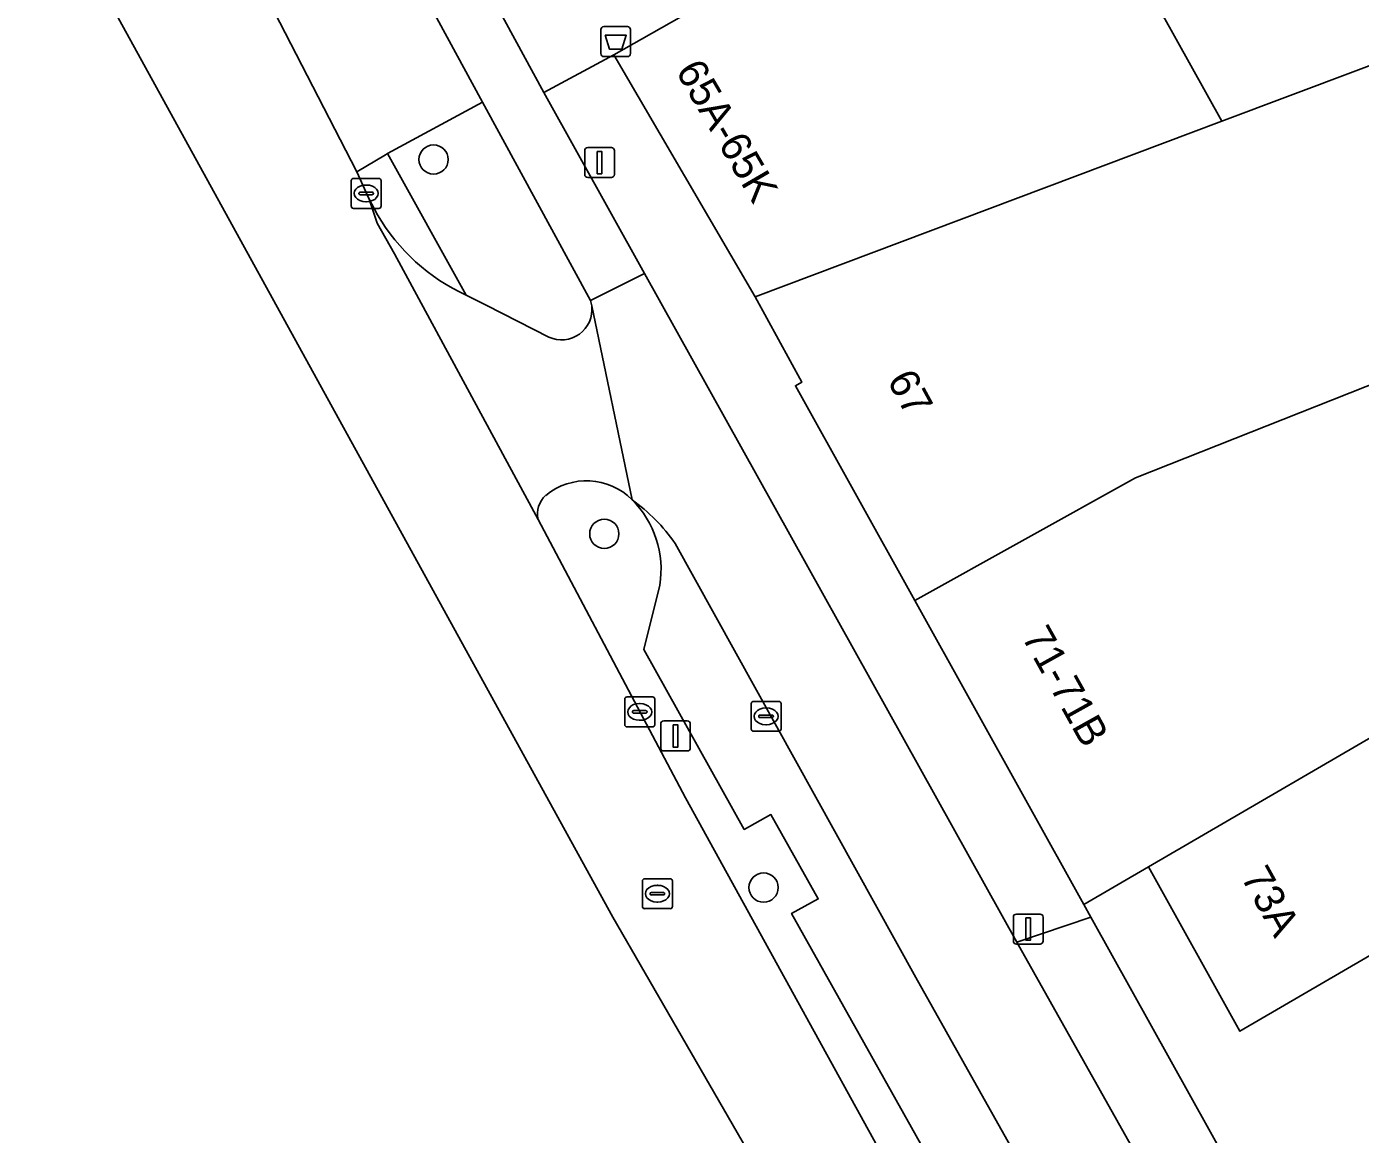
# Model space of a CAD drawing. Extents: x 161881 to 162523, y 381678 to 382381.
# Drawn here: x 162054.54 to 162099.12, y 381947.33 to 381984.36 of the extents above; entities that cross this region are included whole.
import ezdxf

# ---------------------------------------------------------------- set-up
doc = ezdxf.new("R2010")
doc.units = 0
for name, color, linetype in [('IMGEO_Afvalbak', 7, 'Continuous'), ('IMGEO_Berm_groen', 7, 'Continuous'), ('IMGEO_Boom', 7, 'Continuous'), ('IMGEO_Erf', 7, 'Continuous'), ('IMGEO_Fietspad_gesloten', 7, 'Continuous'), ('IMGEO_Fietspad_open', 7, 'Continuous'), ('IMGEO_Kolk', 7, 'Continuous'), ('IMGEO_Lichtmast', 7, 'Continuous'), ('IMGEO_Pand', 7, 'Continuous'), ('IMGEO_Pand_nummerreeks', 7, 'Continuous'), ('IMGEO_Parkeervlak_open', 7, 'Continuous'), ('IMGEO_Rijbaan_lokaal_gesloten', 7, 'Continuous'), ('IMGEO_Rioolput', 7, 'Continuous'), ('IMGEO_Voetpad_open', 7, 'Continuous')]:
    doc.layers.add(name, color=color, linetype=linetype)

msp = doc.modelspace()

# ---------------------------------------------------------------- linework, layer by layer
at = {"layer": 'IMGEO_Afvalbak'}
for p, q in [((162073.733, 381983.46), (162073.733, 381984.26)), ((162073.733, 381984.26), (162073.733, 381983.46)), ((162073.833, 381984.36), (162074.623, 381984.36)), ((162074.623, 381984.36), (162073.833, 381984.36)), ((162074.723, 381984.26), (162074.723, 381983.46)), ((162074.723, 381983.46), (162074.723, 381984.26)), ((162074.623, 381983.36), (162073.833, 381983.36)), ((162073.833, 381983.36), (162074.623, 381983.36))]:
    msp.add_line(p, q, dxfattribs=at)
msp.add_lwpolyline([(162073.876, 381984.074), (162074.58, 381984.074), (162074.431, 381983.604), (162074.025, 381983.604), (162073.876, 381984.074)], dxfattribs=at)
for centre, start, end in [((162073.833, 381984.26), 90, 180), ((162073.833, 381984.26), 90, 180), ((162074.623, 381984.26), 0, 90), ((162074.623, 381984.26), 360, 90), ((162073.833, 381983.46), 180, 270), ((162073.833, 381983.46), 180, 270), ((162074.623, 381983.46), 270, 0), ((162074.623, 381983.46), 270, 0)]:
    msp.add_arc(centre, 0.1, start, end, dxfattribs=at)
at = {"layer": 'IMGEO_Berm_groen'}
for points in [[(162069.775, 381981.832), (162066.606, 381980.116), (162069.236, 381975.383), (162069.927, 381975.036), (162071.998, 381973.982)], [(162073.43, 381975.024), (162073.393, 381975.201), (162069.775, 381981.832)], [(162071.636, 381967.886), (162076.565, 381958.577), (162107.811, 381901.826), (162108.729, 381902.414), (162110.128, 381903.311), (162108.772, 381905.652), (162107.884, 381905.166), (162102.118, 381915.454), (162102.985, 381915.921), (162101.417, 381918.762), (162100.535, 381918.293), (162094.757, 381928.54)], [(162094.757, 381928.54), (162095.649, 381929.029), (162094.05, 381931.846), (162093.19, 381931.352), (162087.448, 381941.624), (162088.219, 381942.206), (162086.738, 381944.939), (162085.861, 381944.447), (162080.108, 381954.721), (162080.998, 381955.203), (162079.42, 381958.024), (162078.528, 381957.526), (162075.168, 381963.546), (162075.702, 381965.694)]]:
    msp.add_lwpolyline(points, dxfattribs=at)
for centre, radius, start, end in [((162072.42, 381974.907), 1.017, 245.498, 6.5853), ((162073.252, 381967.033), 2.147, 44.7404, 129.3923), ((162072.448, 381968.074), 0.833, 132.1236, 193.0227), ((162072.473, 381966.221), 3.272, 350.727, 45.2358)]:
    msp.add_arc(centre, radius, start, end, dxfattribs=at)
at = {"layer": 'IMGEO_Boom'}
for centre in [(162068.144, 381979.919), (162073.85, 381967.407), (162079.174, 381955.584)]:
    msp.add_circle(centre, 0.489, dxfattribs=at)
at = {"layer": 'IMGEO_Erf'}
msp.add_lwpolyline([(162088.878, 381991.295), (162094.493, 381981.199), (162124.179, 381992.364)], dxfattribs=at)
at = {"layer": 'IMGEO_Fietspad_gesloten'}
msp.add_lwpolyline([(162062.41, 381995.394), (162069.775, 381981.832), (162073.393, 381975.201), (162075.194, 381976.109), (162071.825, 381982.158), (162067.605, 381989.931)], dxfattribs=at)
at = {"layer": 'IMGEO_Fietspad_open'}
for points in [[(162075.194, 381976.109), (162073.393, 381975.201), (162073.43, 381975.024), (162074.777, 381968.544)], [(162117.066, 381901.457), (162102.32, 381927.62), (162087.64, 381953.76), (162075.194, 381976.109)], [(162076.214, 381967.086), (162084.266, 381952.579), (162111.528, 381904.042)]]:
    msp.add_lwpolyline(points, dxfattribs=at)
msp.add_arc((162071.422, 381963.8), 5.811, 34.4385, 54.7303, dxfattribs=at)
at = {"layer": 'IMGEO_Kolk'}
for p, q in [((162065.39, 381978.361), (162065.39, 381979.213)), ((162065.465, 381979.287), (162066.317, 381979.287)), ((162065.878, 381979.067), (162065.903, 381979.067)), ((162066.391, 381979.213), (162066.391, 381978.361)), ((162065.649, 381978.781), (162065.649, 381978.793)), ((162066.087, 381978.744), (162065.689, 381978.744)), ((162065.692, 381978.83), (162066.09, 381978.83)), ((162066.133, 381978.793), (162066.133, 381978.781)), ((162066.317, 381978.287), (162065.465, 381978.287)), ((162065.901, 381978.507), (162065.876, 381978.507)), ((162074.534, 381961.028), (162074.534, 381961.88)), ((162074.609, 381961.954), (162075.461, 381961.954)), ((162075.022, 381961.734), (162075.047, 381961.734)), ((162075.535, 381961.88), (162075.535, 381961.028)), ((162078.757, 381960.881), (162078.757, 381961.733)), ((162078.832, 381961.807), (162079.684, 381961.807)), ((162079.758, 381961.733), (162079.758, 381960.881)), ((162074.793, 381961.448), (162074.793, 381961.46)), ((162075.231, 381961.411), (162074.833, 381961.411)), ((162074.836, 381961.497), (162075.234, 381961.497)), ((162075.277, 381961.46), (162075.277, 381961.448)), ((162079.016, 381961.301), (162079.016, 381961.313)), ((162079.454, 381961.264), (162079.056, 381961.264)), ((162079.059, 381961.35), (162079.457, 381961.35)), ((162079.245, 381961.587), (162079.27, 381961.587)), ((162079.5, 381961.313), (162079.5, 381961.301)), ((162075.461, 381960.954), (162074.609, 381960.954)), ((162075.045, 381961.174), (162075.02, 381961.174)), ((162079.684, 381960.807), (162078.832, 381960.807)), ((162079.268, 381961.027), (162079.243, 381961.027))]:
    msp.add_line(p, q, dxfattribs=at)
for points in [[(162065.39, 381978.361), (162065.39, 381979.213)], [(162065.465, 381979.287), (162066.317, 381979.287)], [(162066.391, 381979.213), (162066.391, 381978.361)], [(162066.317, 381978.287), (162065.465, 381978.287)], [(162074.534, 381961.028), (162074.534, 381961.88)], [(162074.609, 381961.954), (162075.461, 381961.954)], [(162075.535, 381961.88), (162075.535, 381961.028)], [(162078.757, 381960.881), (162078.757, 381961.733)], [(162078.832, 381961.807), (162079.684, 381961.807)], [(162079.758, 381961.733), (162079.758, 381960.881)], [(162075.461, 381960.954), (162074.609, 381960.954)], [(162079.684, 381960.807), (162078.832, 381960.807)]]:
    msp.add_lwpolyline(points, dxfattribs=at)
for centre, radius, start, end in [((162065.467, 381979.211), 0.0765, 91.552, 178.448), ((162065.467, 381979.211), 0.0765, 91.552, 178.448), ((162066.315, 381979.211), 0.0765, 1.552, 88.448), ((162066.315, 381979.211), 0.0765, 1.552, 88.448), ((162065.689, 381978.79), 0.0403, 85.8775, 175.7526), ((162065.686, 381978.78), 0.0366, 178.938, 274.7102), ((162066.09, 381978.787), 0.043, 264.8664, 352.4533), ((162066.094, 381978.792), 0.0386, 1.7309, 96.639), ((162065.467, 381978.363), 0.0765, 181.552, 268.448), ((162065.467, 381978.363), 0.0765, 181.552, 268.448), ((162066.315, 381978.363), 0.0765, 271.552, 358.448), ((162066.315, 381978.363), 0.0765, 271.552, 358.448), ((162074.611, 381961.878), 0.0765, 91.552, 178.448), ((162074.611, 381961.878), 0.0765, 91.552, 178.448), ((162075.459, 381961.878), 0.0765, 1.552, 88.448), ((162075.459, 381961.878), 0.0765, 1.552, 88.448), ((162078.834, 381961.731), 0.0765, 91.552, 178.448), ((162078.834, 381961.731), 0.0765, 91.552, 178.448), ((162079.682, 381961.731), 0.0765, 1.552, 88.448), ((162079.682, 381961.731), 0.0765, 1.552, 88.448), ((162074.833, 381961.457), 0.0403, 85.8775, 175.7526), ((162074.83, 381961.447), 0.0366, 178.938, 274.7102), ((162075.234, 381961.454), 0.043, 264.8664, 352.4533), ((162075.238, 381961.459), 0.0386, 1.7309, 96.639), ((162079.056, 381961.31), 0.0403, 85.8775, 175.7526), ((162079.053, 381961.3), 0.0366, 178.938, 274.7102), ((162079.457, 381961.307), 0.043, 264.8664, 352.4533), ((162079.461, 381961.312), 0.0386, 1.7309, 96.639), ((162074.611, 381961.03), 0.0765, 181.552, 268.448), ((162074.611, 381961.03), 0.0765, 181.552, 268.448), ((162075.459, 381961.03), 0.0765, 271.552, 358.448), ((162075.459, 381961.03), 0.0765, 271.552, 358.448), ((162078.834, 381960.883), 0.0765, 181.552, 268.448), ((162078.834, 381960.883), 0.0765, 181.552, 268.448), ((162079.682, 381960.883), 0.0765, 271.552, 358.448), ((162079.682, 381960.883), 0.0765, 271.552, 358.448)]:
    msp.add_arc(centre, radius, start, end, dxfattribs=at)
for centre, major_axis, ratio, start_param, end_param in [((162065.877, 381978.787), (-0.387, 0.002), 0.722429, 4.712389, 7.853982), ((162065.902, 381978.787), (-0.39, 0.002), 0.717154, 1.570796, 4.712389), ((162075.021, 381961.454), (-0.387, 0.002), 0.722429, 4.712389, 7.853982), ((162075.046, 381961.454), (-0.39, 0.002), 0.717154, 1.570796, 4.712389), ((162079.244, 381961.307), (-0.387, 0.002), 0.722429, 4.712389, 7.853982), ((162079.269, 381961.307), (-0.39, 0.002), 0.717154, 1.570796, 4.712389)]:
    msp.add_ellipse(centre, major_axis=major_axis, ratio=ratio, start_param=start_param, end_param=end_param, dxfattribs=at)
at = {"layer": 'IMGEO_Lichtmast'}
for p, q in [((162073.195, 381979.417), (162073.195, 381980.217)), ((162073.195, 381980.217), (162073.195, 381979.417)), ((162073.295, 381980.317), (162074.085, 381980.317)), ((162074.085, 381980.317), (162073.295, 381980.317)), ((162074.185, 381980.217), (162074.185, 381979.417)), ((162074.185, 381979.417), (162074.185, 381980.217)), ((162074.085, 381979.317), (162073.295, 381979.317)), ((162073.295, 381979.317), (162074.085, 381979.317)), ((162075.734, 381960.251), (162075.734, 381961.051)), ((162075.734, 381961.051), (162075.734, 381960.251)), ((162075.834, 381961.151), (162076.624, 381961.151)), ((162076.624, 381961.151), (162075.834, 381961.151)), ((162076.724, 381961.051), (162076.724, 381960.251)), ((162076.724, 381960.251), (162076.724, 381961.051)), ((162076.624, 381960.151), (162075.834, 381960.151)), ((162075.834, 381960.151), (162076.624, 381960.151)), ((162087.522, 381953.796), (162087.522, 381954.596)), ((162087.522, 381954.596), (162087.522, 381953.796)), ((162087.622, 381954.696), (162088.412, 381954.696)), ((162088.412, 381954.696), (162087.622, 381954.696)), ((162088.512, 381954.596), (162088.512, 381953.796)), ((162088.512, 381953.796), (162088.512, 381954.596)), ((162088.412, 381953.696), (162087.622, 381953.696)), ((162087.622, 381953.696), (162088.412, 381953.696))]:
    msp.add_line(p, q, dxfattribs=at)
for points in [[(162073.615, 381980.192), (162073.765, 381980.192), (162073.765, 381979.442), (162073.615, 381979.442), (162073.615, 381980.192)], [(162076.154, 381961.026), (162076.304, 381961.026), (162076.304, 381960.276), (162076.154, 381960.276), (162076.154, 381961.026)], [(162087.942, 381954.571), (162088.092, 381954.571), (162088.092, 381953.821), (162087.942, 381953.821), (162087.942, 381954.571)]]:
    msp.add_lwpolyline(points, dxfattribs=at)
for centre, start, end in [((162073.295, 381980.217), 90, 180), ((162073.295, 381980.217), 90, 180), ((162074.085, 381980.217), 0, 90), ((162074.085, 381980.217), 360, 90), ((162073.295, 381979.417), 180, 270), ((162073.295, 381979.417), 180, 270), ((162074.085, 381979.417), 270, 0), ((162074.085, 381979.417), 270, 0), ((162075.834, 381961.051), 90, 180), ((162075.834, 381961.051), 90, 180), ((162076.624, 381961.051), 0, 90), ((162076.624, 381961.051), 360, 90), ((162075.834, 381960.251), 180, 270), ((162075.834, 381960.251), 180, 270), ((162076.624, 381960.251), 270, 0), ((162076.624, 381960.251), 270, 0), ((162087.622, 381954.596), 90, 180), ((162087.622, 381954.596), 90, 180), ((162088.412, 381954.596), 0, 90), ((162088.412, 381954.596), 360, 90), ((162087.622, 381953.796), 180, 270), ((162087.622, 381953.796), 180, 270), ((162088.412, 381953.796), 270, 0), ((162088.412, 381953.796), 270, 0)]:
    msp.add_arc(centre, 0.1, start, end, dxfattribs=at)
at = {"layer": 'IMGEO_Pand'}
for points in [[(162112.686, 381977.996), (162116.818, 381979.55), (162115.138, 381984.016), (162125.323, 381987.847), (162124.179, 381992.364), (162094.493, 381981.199), (162078.888, 381975.33), (162080.448, 381972.475), (162080.234, 381972.356), (162084.224, 381965.182), (162091.602, 381969.28), (162103.707, 381974.071), (162106.111, 381975.02), (162105.938, 381975.458)], [(162088.878, 381991.295), (162084.239, 381988.715), (162084.06, 381989.037), (162074.163, 381983.415), (162078.888, 381975.33), (162094.493, 381981.199)], [(162127.156, 381972.918), (162124.971, 381978.729), (162124.585, 381979.754), (162122.531, 381978.989), (162106.819, 381973.14), (162106.111, 381975.02), (162103.707, 381974.071), (162091.602, 381969.28), (162084.224, 381965.182), (162089.877, 381955.018), (162092.037, 381956.277), (162101.493, 381961.784), (162108.867, 381964.516), (162110.177, 381965.001), (162110.109, 381965.182), (162110.039, 381965.369), (162109.673, 381966.342)], [(162101.493, 381961.784), (162092.037, 381956.277), (162095.093, 381950.781), (162102.018, 381954.814), (162100.084, 381958.29), (162102.644, 381959.714)], [(162102.018, 381954.814), (162095.093, 381950.781), (162092.037, 381956.277), (162089.877, 381955.018), (162090.11, 381954.599), (162104.077, 381929.487), (162104.562, 381928.615), (162108.932, 381931.046), (162118.036, 381936.109), (162127.861, 381940.832), (162139.038, 381946.204), (162132.287, 381958.988), (162134.209, 381959.922), (162134.174, 381960.054), (162132.237, 381959.113), (162132.047, 381959.477), (162123.76, 381955.478), (162115.472, 381951.478), (162112.537, 381950.052), (162112.612, 381949.9), (162106.444, 381946.857)]]:
    msp.add_lwpolyline(points, close=True, dxfattribs=at)
at = {"layer": 'IMGEO_Parkeervlak_open'}
msp.add_lwpolyline([(162075.702, 381965.694), (162075.168, 381963.546), (162078.528, 381957.526), (162079.42, 381958.024), (162080.998, 381955.203), (162080.108, 381954.721), (162085.861, 381944.447), (162086.738, 381944.939), (162088.219, 381942.206), (162087.448, 381941.624), (162093.19, 381931.352), (162094.05, 381931.846), (162095.649, 381929.029), (162094.757, 381928.54), (162100.535, 381918.293), (162101.417, 381918.762), (162102.985, 381915.921), (162102.118, 381915.454), (162107.884, 381905.166), (162108.772, 381905.652), (162110.128, 381903.311), (162111.528, 381904.042), (162084.266, 381952.579), (162076.214, 381967.086)], dxfattribs=at)
for centre, radius, start, end in [((162071.422, 381963.8), 5.811, 34.4385, 54.7303), ((162072.473, 381966.221), 3.272, 350.727, 45.2358)]:
    msp.add_arc(centre, radius, start, end, dxfattribs=at)
at = {"layer": 'IMGEO_Rijbaan_lokaal_gesloten'}
for points in [[(161957.883, 382126.571), (162018.616, 382046.024), (162020.205, 382044.026), (162035.676, 382024.566), (162039.393, 382017.803), (162056.257, 381987.116), (162074.133, 381954.589), (162112.413, 381888.285), (162135.308, 381862.267), (162145.259, 381854.842)], [(162120.092, 381883.14), (162118.816, 381884.72), (162116.672, 381887.684), (162107.811, 381901.826), (162076.565, 381958.577), (162071.636, 381967.886), (162066.835, 381976.766), (162066.256, 381977.793), (162065.992, 381978.592), (162065.582, 381979.503), (162062.076, 381986.301), (162058.206, 381993.875), (162057.987, 381994.304)], [(162066.265, 381978.073), (162065.992, 381978.592), (162066.256, 381977.793), (162066.835, 381976.766), (162071.636, 381967.886)], [(162071.998, 381973.982), (162069.927, 381975.036), (162069.236, 381975.383)], [(162074.777, 381968.544), (162073.43, 381975.024)]]:
    msp.add_lwpolyline(points, dxfattribs=at)
for centre, radius, start, end in [((162072.015, 381981.438), 6.662, 210.337, 245.3464), ((162072.42, 381974.907), 1.017, 245.498, 6.5853), ((162073.252, 381967.033), 2.147, 44.7404, 129.3923), ((162072.448, 381968.074), 0.833, 132.1236, 193.0227)]:
    msp.add_arc(centre, radius, start, end, dxfattribs=at)
at = {"layer": 'IMGEO_Rioolput'}
for p, q in [((162075.198, 381955.878), (162076.05, 381955.878)), ((162075.123, 381954.952), (162075.123, 381955.804)), ((162075.611, 381955.658), (162075.636, 381955.658)), ((162076.124, 381955.804), (162076.124, 381954.952)), ((162075.382, 381955.372), (162075.382, 381955.384)), ((162075.82, 381955.335), (162075.422, 381955.335)), ((162075.425, 381955.421), (162075.823, 381955.421)), ((162075.634, 381955.098), (162075.609, 381955.098)), ((162075.866, 381955.384), (162075.866, 381955.372)), ((162076.05, 381954.878), (162075.198, 381954.878))]:
    msp.add_line(p, q, dxfattribs=at)
for points in [[(162075.198, 381955.878), (162076.05, 381955.878)], [(162075.123, 381954.952), (162075.123, 381955.804)], [(162076.124, 381955.804), (162076.124, 381954.952)], [(162076.05, 381954.878), (162075.198, 381954.878)]]:
    msp.add_lwpolyline(points, dxfattribs=at)
for centre, radius, start, end in [((162075.2, 381955.802), 0.0765, 91.552, 178.448), ((162075.2, 381955.802), 0.0765, 91.552, 178.448), ((162076.048, 381955.802), 0.0765, 1.552, 88.448), ((162076.048, 381955.802), 0.0765, 1.552, 88.448), ((162075.422, 381955.381), 0.0403, 85.8775, 175.7526), ((162075.419, 381955.371), 0.0366, 178.938, 274.7102), ((162075.823, 381955.378), 0.043, 264.8664, 352.4533), ((162075.827, 381955.383), 0.0386, 1.7309, 96.639), ((162075.2, 381954.954), 0.0765, 181.552, 268.448), ((162075.2, 381954.954), 0.0765, 181.552, 268.448), ((162076.048, 381954.954), 0.0765, 271.552, 358.448), ((162076.048, 381954.954), 0.0765, 271.552, 358.448)]:
    msp.add_arc(centre, radius, start, end, dxfattribs=at)
for centre, major_axis, ratio, start_param, end_param in [((162075.61, 381955.378), (-0.387, 0.002), 0.722429, 4.712389, 7.853982), ((162075.635, 381955.378), (-0.39, 0.002), 0.717154, 1.570796, 4.712389)]:
    msp.add_ellipse(centre, major_axis=major_axis, ratio=ratio, start_param=start_param, end_param=end_param, dxfattribs=at)
at = {"layer": 'IMGEO_Voetpad_open'}
for points in [[(162087.895, 381992.959), (162087.193, 381994.544), (162085.897, 381996.336), (162083.946, 382000.814), (162064.377, 381995.878), (162067.605, 381989.931), (162071.825, 381982.158), (162074.163, 381983.415), (162084.06, 381989.037), (162084.239, 381988.715), (162088.878, 381991.295)], [(162062.41, 381995.394), (162058.028, 381994.314), (162057.987, 381994.304), (162058.206, 381993.875), (162062.076, 381986.301), (162065.582, 381979.503), (162066.538, 381980.079), (162066.606, 381980.116), (162069.775, 381981.832)], [(162074.163, 381983.415), (162071.825, 381982.158), (162075.194, 381976.109), (162087.64, 381953.76), (162090.11, 381954.599), (162089.877, 381955.018), (162084.224, 381965.182), (162080.234, 381972.356), (162080.448, 381972.475), (162078.888, 381975.33)], [(162090.11, 381954.599), (162087.64, 381953.76), (162102.32, 381927.62), (162104.077, 381929.487)]]:
    msp.add_lwpolyline(points, close=True, dxfattribs=at)
for points in [[(162066.606, 381980.116), (162066.538, 381980.079), (162065.582, 381979.503), (162065.992, 381978.592), (162066.265, 381978.073)], [(162069.236, 381975.383), (162066.606, 381980.116)]]:
    msp.add_lwpolyline(points, dxfattribs=at)
msp.add_arc((162072.015, 381981.438), 6.662, 210.337, 245.3464, dxfattribs=at)

# ---------------------------------------------------------------- texts
at = {"layer": 'IMGEO_Pand_nummerreeks'}
for s, rotation, p in [('65A-65K', 300.3035, (162076.214, 381982.878)), ('67', 298.6534, (162083.283, 381972.542)), ('71-71B', 299.0831, (162087.783, 381963.968)), ('73A', 299.0758, (162095.109, 381955.938))]:
    msp.add_text(s, height=1, rotation=rotation, dxfattribs=at).set_placement(p)

doc.saveas('drawing.dxf')
